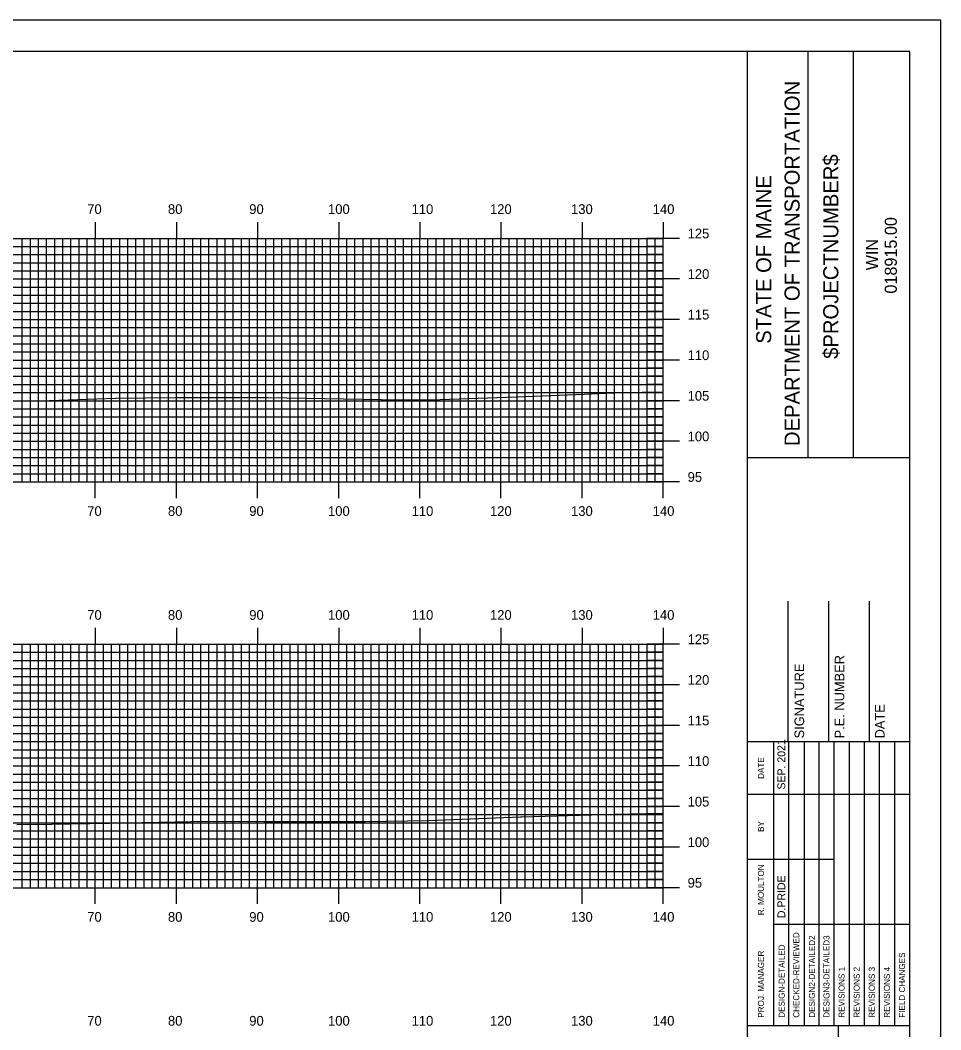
# Model space of a CAD drawing. Extents: x 1787763 to 1788106, y 442591 to 442811.
# Drawn here: x 1787989.4 to 1788102.8, y 442686.2 to 442810.5 of the extents above; entities that cross this region are included whole.
import ezdxf

# ---------------------------------------------------------------- set-up
doc = ezdxf.new("R2010")
doc.units = 0
for name, color, linetype in [('BORDER', 7, 'Continuous'), ('H_V ANNOTATION', 7, 'Continuous'), ('MAJOR', 7, 'Continuous'), ('MINOR', 7, 'Continuous'), ('PLOT BOUNDARY', 7, 'Continuous'), ('S_Roadway_Centerline', 7, 'Continuous')]:
    doc.layers.add(name, color=color, linetype=linetype)

msp = doc.modelspace()

# ---------------------------------------------------------------- linework, layer by layer
at = {"layer": 'BORDER'}
for p, q in [((1788079.02, 442596.67), (1788079.02, 442806.67)), ((1788086.47, 442756.66), (1788086.47, 442806.66)), ((1788092.06, 442756.66), (1788092.06, 442806.66)), ((1788079.02, 442756.65), (1788099.02, 442756.65)), ((1788084.02, 442721.67), (1788084.02, 442738.97)), ((1788089.02, 442721.67), (1788089.02, 442738.97)), ((1788094.02, 442721.67), (1788094.02, 442738.97)), ((1788079.02, 442721.67), (1788099.02, 442721.67)), ((1788079.02, 442686.67), (1788099.02, 442686.67)), ((1788090.2, 442616.67), (1788090.2, 442686.67))]:
    msp.add_line(p, q, dxfattribs=at)
msp.add_lwpolyline([(1787779.02, 442596.67), (1788099.02, 442596.67), (1788099.02, 442806.67), (1787779.02, 442806.67)], close=True, dxfattribs=at)
for points in [[(1788082.25, 442715.17), (1788082.25, 442721.67)], [(1788084.11, 442686.68), (1788084.11, 442721.67)], [(1788085.98, 442721.67), (1788085.98, 442686.68)], [(1788087.84, 442686.68), (1788087.84, 442721.67)], [(1788089.7, 442686.68), (1788089.7, 442721.67)], [(1788091.57, 442686.68), (1788091.57, 442721.67)], [(1788093.43, 442686.68), (1788093.43, 442721.67)], [(1788095.29, 442686.68), (1788095.29, 442721.67)], [(1788097.16, 442686.68), (1788097.16, 442721.67)], [(1788082.25, 442686.68), (1788082.25, 442720.26)], [(1788079.02, 442715.17), (1788099.02, 442715.17)], [(1788079.02, 442707.17), (1788082.25, 442707.17)], [(1788082.25, 442707.17), (1788089.7, 442707.17)], [(1788082.25, 442699.17), (1788099.02, 442699.17)]]:
    msp.add_lwpolyline(points, dxfattribs=at)
at = {"layer": 'MAJOR'}
for p, q in [((1787998.62, 442785.67), (1787998.62, 442783.67)), ((1788008.62, 442785.67), (1788008.62, 442783.67)), ((1788018.62, 442785.67), (1788018.62, 442783.67)), ((1788028.62, 442785.67), (1788028.62, 442783.67)), ((1788038.62, 442785.67), (1788038.62, 442783.67)), ((1788048.62, 442785.67), (1788048.62, 442783.67)), ((1788058.62, 442785.67), (1788058.62, 442783.67)), ((1788068.62, 442785.67), (1788068.62, 442783.67)), ((1787788.62, 442783.67), (1788068.62, 442783.67)), ((1787788.62, 442783.67), (1788068.62, 442783.67)), ((1787998.62, 442753.67), (1787998.62, 442783.67)), ((1788008.62, 442753.67), (1788008.62, 442783.67)), ((1788018.62, 442753.67), (1788018.62, 442783.67)), ((1788028.62, 442753.67), (1788028.62, 442783.67)), ((1788038.62, 442753.67), (1788038.62, 442783.67)), ((1788048.62, 442753.67), (1788048.62, 442783.67)), ((1788058.62, 442753.67), (1788058.62, 442783.67)), ((1788070.62, 442783.67), (1788066.61, 442783.67)), ((1788068.62, 442753.67), (1788068.62, 442783.67)), ((1788068.62, 442753.67), (1788068.62, 442783.67)), ((1787788.62, 442778.67), (1788068.62, 442778.67)), ((1788070.62, 442778.67), (1788066.61, 442778.67)), ((1787788.62, 442773.67), (1788068.62, 442773.67)), ((1788070.62, 442773.67), (1788066.61, 442773.67)), ((1787788.62, 442768.67), (1788068.62, 442768.67)), ((1788070.62, 442768.67), (1788066.61, 442768.67)), ((1787788.62, 442763.67), (1788068.62, 442763.67)), ((1788070.62, 442763.67), (1788066.61, 442763.67)), ((1787788.62, 442758.67), (1788068.62, 442758.67)), ((1788070.62, 442758.67), (1788066.61, 442758.67)), ((1787788.62, 442753.67), (1788068.62, 442753.67)), ((1787788.62, 442753.67), (1788068.62, 442753.67)), ((1787998.62, 442751.66), (1787998.62, 442753.67)), ((1788008.62, 442751.66), (1788008.62, 442753.67)), ((1788018.62, 442751.66), (1788018.62, 442753.67)), ((1788028.62, 442751.66), (1788028.62, 442753.67)), ((1788038.62, 442751.66), (1788038.62, 442753.67)), ((1788048.62, 442751.66), (1788048.62, 442753.67)), ((1788058.62, 442751.66), (1788058.62, 442753.67)), ((1788070.62, 442753.67), (1788066.61, 442753.67)), ((1788068.62, 442751.66), (1788068.62, 442753.67)), ((1787998.62, 442735.67), (1787998.62, 442733.67)), ((1788008.62, 442735.67), (1788008.62, 442733.67)), ((1788018.62, 442735.67), (1788018.62, 442733.67)), ((1788028.62, 442735.67), (1788028.62, 442733.67)), ((1788038.62, 442735.67), (1788038.62, 442733.67)), ((1788048.62, 442735.67), (1788048.62, 442733.67)), ((1788058.62, 442735.67), (1788058.62, 442733.67)), ((1788068.62, 442735.67), (1788068.62, 442733.67)), ((1787788.62, 442733.67), (1788068.62, 442733.67)), ((1787788.62, 442733.67), (1788068.62, 442733.67)), ((1787998.62, 442703.67), (1787998.62, 442733.67)), ((1788008.62, 442703.67), (1788008.62, 442733.67)), ((1788018.62, 442703.67), (1788018.62, 442733.67)), ((1788028.62, 442703.67), (1788028.62, 442733.67)), ((1788038.62, 442703.67), (1788038.62, 442733.67)), ((1788048.62, 442703.67), (1788048.62, 442733.67)), ((1788058.62, 442703.67), (1788058.62, 442733.67)), ((1788070.62, 442733.67), (1788066.61, 442733.67)), ((1788068.62, 442703.67), (1788068.62, 442733.67)), ((1788068.62, 442703.67), (1788068.62, 442733.67)), ((1787788.62, 442728.67), (1788068.62, 442728.67)), ((1788070.62, 442728.67), (1788066.61, 442728.67)), ((1787788.62, 442723.67), (1788068.62, 442723.67)), ((1788070.62, 442723.67), (1788066.61, 442723.67)), ((1787788.62, 442718.67), (1788068.62, 442718.67)), ((1788070.62, 442718.67), (1788066.61, 442718.67)), ((1787788.62, 442713.67), (1788068.62, 442713.67)), ((1788070.62, 442713.67), (1788066.61, 442713.67)), ((1787788.62, 442708.67), (1788068.62, 442708.67)), ((1788070.62, 442708.67), (1788066.61, 442708.67)), ((1787788.62, 442703.67), (1788068.62, 442703.67)), ((1787788.62, 442703.67), (1788068.62, 442703.67)), ((1787998.62, 442701.66), (1787998.62, 442703.67)), ((1788008.62, 442701.66), (1788008.62, 442703.67)), ((1788018.62, 442701.66), (1788018.62, 442703.67)), ((1788028.62, 442701.66), (1788028.62, 442703.67)), ((1788038.62, 442701.66), (1788038.62, 442703.67)), ((1788048.62, 442701.66), (1788048.62, 442703.67)), ((1788058.62, 442701.66), (1788058.62, 442703.67)), ((1788070.62, 442703.67), (1788066.61, 442703.67)), ((1788068.62, 442701.66), (1788068.62, 442703.67))]:
    msp.add_line(p, q, dxfattribs=at)
at = {"layer": 'MINOR'}
for p, q in [((1787989.62, 442753.67), (1787989.62, 442783.67)), ((1787990.62, 442753.67), (1787990.62, 442783.67)), ((1787991.62, 442753.67), (1787991.62, 442783.67)), ((1787992.62, 442753.67), (1787992.62, 442783.67)), ((1787993.62, 442753.67), (1787993.62, 442783.67)), ((1787994.62, 442753.67), (1787994.62, 442783.67)), ((1787995.62, 442753.67), (1787995.62, 442783.67)), ((1787996.62, 442753.67), (1787996.62, 442783.67)), ((1787997.62, 442753.67), (1787997.62, 442783.67)), ((1787999.62, 442753.67), (1787999.62, 442783.67)), ((1788000.62, 442753.67), (1788000.62, 442783.67)), ((1788001.62, 442753.67), (1788001.62, 442783.67)), ((1788002.62, 442753.67), (1788002.62, 442783.67)), ((1788003.62, 442753.67), (1788003.62, 442783.67)), ((1788004.62, 442753.67), (1788004.62, 442783.67)), ((1788005.62, 442753.67), (1788005.62, 442783.67)), ((1788006.62, 442753.67), (1788006.62, 442783.67)), ((1788007.62, 442753.67), (1788007.62, 442783.67)), ((1788009.62, 442753.67), (1788009.62, 442783.67)), ((1788010.62, 442753.67), (1788010.62, 442783.67)), ((1788011.62, 442753.67), (1788011.62, 442783.67)), ((1788012.62, 442753.67), (1788012.62, 442783.67)), ((1788013.62, 442753.67), (1788013.62, 442783.67)), ((1788014.62, 442753.67), (1788014.62, 442783.67)), ((1788015.62, 442753.67), (1788015.62, 442783.67)), ((1788016.62, 442753.67), (1788016.62, 442783.67)), ((1788017.62, 442753.67), (1788017.62, 442783.67)), ((1788019.62, 442753.67), (1788019.62, 442783.67)), ((1788020.62, 442753.67), (1788020.62, 442783.67)), ((1788021.62, 442753.67), (1788021.62, 442783.67)), ((1788022.62, 442753.67), (1788022.62, 442783.67)), ((1788023.62, 442753.67), (1788023.62, 442783.67)), ((1788024.62, 442753.67), (1788024.62, 442783.67)), ((1788025.62, 442753.67), (1788025.62, 442783.67)), ((1788026.62, 442753.67), (1788026.62, 442783.67)), ((1788027.62, 442753.67), (1788027.62, 442783.67)), ((1788029.62, 442753.67), (1788029.62, 442783.67)), ((1788030.62, 442753.67), (1788030.62, 442783.67)), ((1788031.62, 442753.67), (1788031.62, 442783.67)), ((1788032.62, 442753.67), (1788032.62, 442783.67)), ((1788033.62, 442753.67), (1788033.62, 442783.67)), ((1788034.62, 442753.67), (1788034.62, 442783.67)), ((1788035.62, 442753.67), (1788035.62, 442783.67)), ((1788036.62, 442753.67), (1788036.62, 442783.67)), ((1788037.62, 442753.67), (1788037.62, 442783.67)), ((1788039.62, 442753.67), (1788039.62, 442783.67)), ((1788040.62, 442753.67), (1788040.62, 442783.67)), ((1788041.62, 442753.67), (1788041.62, 442783.67)), ((1788042.62, 442753.67), (1788042.62, 442783.67)), ((1788043.62, 442753.67), (1788043.62, 442783.67)), ((1788044.62, 442753.67), (1788044.62, 442783.67)), ((1788045.62, 442753.67), (1788045.62, 442783.67)), ((1788046.62, 442753.67), (1788046.62, 442783.67)), ((1788047.62, 442753.67), (1788047.62, 442783.67)), ((1788049.62, 442753.67), (1788049.62, 442783.67)), ((1788050.62, 442753.67), (1788050.62, 442783.67)), ((1788051.62, 442753.67), (1788051.62, 442783.67)), ((1788052.62, 442753.67), (1788052.62, 442783.67)), ((1788053.62, 442753.67), (1788053.62, 442783.67)), ((1788054.62, 442753.67), (1788054.62, 442783.67)), ((1788055.62, 442753.67), (1788055.62, 442783.67)), ((1788056.62, 442753.67), (1788056.62, 442783.67)), ((1788057.62, 442753.67), (1788057.62, 442783.67)), ((1788059.62, 442753.67), (1788059.62, 442783.67)), ((1788060.62, 442753.67), (1788060.62, 442783.67)), ((1788061.62, 442753.67), (1788061.62, 442783.67)), ((1788062.62, 442753.67), (1788062.62, 442783.67)), ((1788063.62, 442753.67), (1788063.62, 442783.67)), ((1788064.62, 442753.67), (1788064.62, 442783.67)), ((1788065.62, 442753.67), (1788065.62, 442783.67)), ((1788066.62, 442753.67), (1788066.62, 442783.67)), ((1788067.62, 442753.67), (1788067.62, 442783.67)), ((1787788.62, 442782.67), (1788068.62, 442782.67)), ((1788068.62, 442782.67), (1788066.61, 442782.67)), ((1787788.62, 442781.67), (1788068.62, 442781.67)), ((1788068.62, 442781.67), (1788066.61, 442781.67)), ((1787788.62, 442780.67), (1788068.62, 442780.67)), ((1788068.62, 442780.67), (1788066.61, 442780.67)), ((1787788.62, 442779.67), (1788068.62, 442779.67)), ((1788068.62, 442779.67), (1788066.61, 442779.67)), ((1787788.62, 442777.67), (1788068.62, 442777.67)), ((1788068.62, 442777.67), (1788066.61, 442777.67)), ((1787788.62, 442776.67), (1788068.62, 442776.67)), ((1788068.62, 442776.67), (1788066.61, 442776.67)), ((1787788.62, 442775.67), (1788068.62, 442775.67)), ((1788068.62, 442775.67), (1788066.61, 442775.67)), ((1787788.62, 442774.67), (1788068.62, 442774.67)), ((1788068.62, 442774.67), (1788066.61, 442774.67)), ((1787788.62, 442772.67), (1788068.62, 442772.67)), ((1788068.62, 442772.67), (1788066.61, 442772.67)), ((1787788.62, 442771.67), (1788068.62, 442771.67)), ((1788068.62, 442771.67), (1788066.61, 442771.67)), ((1787788.62, 442770.67), (1788068.62, 442770.67)), ((1788068.62, 442770.67), (1788066.61, 442770.67)), ((1787788.62, 442769.67), (1788068.62, 442769.67)), ((1788068.62, 442769.67), (1788066.61, 442769.67)), ((1787788.62, 442767.67), (1788068.62, 442767.67)), ((1788068.62, 442767.67), (1788066.61, 442767.67)), ((1787788.62, 442766.67), (1788068.62, 442766.67)), ((1788068.62, 442766.67), (1788066.61, 442766.67)), ((1787788.62, 442765.67), (1788068.62, 442765.67)), ((1788068.62, 442765.67), (1788066.61, 442765.67)), ((1787788.62, 442764.67), (1788068.62, 442764.67)), ((1788068.62, 442764.67), (1788066.61, 442764.67)), ((1787788.62, 442762.67), (1788068.62, 442762.67)), ((1788068.62, 442762.67), (1788066.61, 442762.67)), ((1787788.62, 442761.67), (1788068.62, 442761.67)), ((1788068.62, 442761.67), (1788066.61, 442761.67)), ((1787788.62, 442760.67), (1788068.62, 442760.67)), ((1788068.62, 442760.67), (1788066.61, 442760.67)), ((1787788.62, 442759.67), (1788068.62, 442759.67)), ((1788068.62, 442759.67), (1788066.61, 442759.67)), ((1787788.62, 442757.67), (1788068.62, 442757.67)), ((1788068.62, 442757.67), (1788066.61, 442757.67)), ((1787788.62, 442756.67), (1788068.62, 442756.67)), ((1788068.62, 442756.67), (1788066.61, 442756.67)), ((1787788.62, 442755.67), (1788068.62, 442755.67)), ((1788068.62, 442755.67), (1788066.61, 442755.67)), ((1787788.62, 442754.67), (1788068.62, 442754.67)), ((1788068.62, 442754.67), (1788066.61, 442754.67)), ((1787788.62, 442732.67), (1788068.62, 442732.67)), ((1787989.62, 442703.67), (1787989.62, 442733.67)), ((1787990.62, 442703.67), (1787990.62, 442733.67)), ((1787991.62, 442703.67), (1787991.62, 442733.67)), ((1787992.62, 442703.67), (1787992.62, 442733.67)), ((1787993.62, 442703.67), (1787993.62, 442733.67)), ((1787994.62, 442703.67), (1787994.62, 442733.67)), ((1787995.62, 442703.67), (1787995.62, 442733.67)), ((1787996.62, 442703.67), (1787996.62, 442733.67)), ((1787997.62, 442703.67), (1787997.62, 442733.67)), ((1787999.62, 442703.67), (1787999.62, 442733.67)), ((1788000.62, 442703.67), (1788000.62, 442733.67)), ((1788001.62, 442703.67), (1788001.62, 442733.67)), ((1788002.62, 442703.67), (1788002.62, 442733.67)), ((1788003.62, 442703.67), (1788003.62, 442733.67)), ((1788004.62, 442703.67), (1788004.62, 442733.67)), ((1788005.62, 442703.67), (1788005.62, 442733.67)), ((1788006.62, 442703.67), (1788006.62, 442733.67)), ((1788007.62, 442703.67), (1788007.62, 442733.67)), ((1788009.62, 442703.67), (1788009.62, 442733.67)), ((1788010.62, 442703.67), (1788010.62, 442733.67)), ((1788011.62, 442703.67), (1788011.62, 442733.67)), ((1788012.62, 442703.67), (1788012.62, 442733.67)), ((1788013.62, 442703.67), (1788013.62, 442733.67)), ((1788014.62, 442703.67), (1788014.62, 442733.67)), ((1788015.62, 442703.67), (1788015.62, 442733.67)), ((1788016.62, 442703.67), (1788016.62, 442733.67)), ((1788017.62, 442703.67), (1788017.62, 442733.67)), ((1788019.62, 442703.67), (1788019.62, 442733.67)), ((1788020.62, 442703.67), (1788020.62, 442733.67)), ((1788021.62, 442703.67), (1788021.62, 442733.67)), ((1788022.62, 442703.67), (1788022.62, 442733.67)), ((1788023.62, 442703.67), (1788023.62, 442733.67)), ((1788024.62, 442703.67), (1788024.62, 442733.67)), ((1788025.62, 442703.67), (1788025.62, 442733.67)), ((1788026.62, 442703.67), (1788026.62, 442733.67)), ((1788027.62, 442703.67), (1788027.62, 442733.67)), ((1788029.62, 442703.67), (1788029.62, 442733.67)), ((1788030.62, 442703.67), (1788030.62, 442733.67)), ((1788031.62, 442703.67), (1788031.62, 442733.67)), ((1788032.62, 442703.67), (1788032.62, 442733.67)), ((1788033.62, 442703.67), (1788033.62, 442733.67)), ((1788034.62, 442703.67), (1788034.62, 442733.67)), ((1788035.62, 442703.67), (1788035.62, 442733.67)), ((1788036.62, 442703.67), (1788036.62, 442733.67)), ((1788037.62, 442703.67), (1788037.62, 442733.67)), ((1788039.62, 442703.67), (1788039.62, 442733.67)), ((1788040.62, 442703.67), (1788040.62, 442733.67)), ((1788041.62, 442703.67), (1788041.62, 442733.67)), ((1788042.62, 442703.67), (1788042.62, 442733.67)), ((1788043.62, 442703.67), (1788043.62, 442733.67)), ((1788044.62, 442703.67), (1788044.62, 442733.67)), ((1788045.62, 442703.67), (1788045.62, 442733.67)), ((1788046.62, 442703.67), (1788046.62, 442733.67)), ((1788047.62, 442703.67), (1788047.62, 442733.67)), ((1788049.62, 442703.67), (1788049.62, 442733.67)), ((1788050.62, 442703.67), (1788050.62, 442733.67)), ((1788051.62, 442703.67), (1788051.62, 442733.67)), ((1788052.62, 442703.67), (1788052.62, 442733.67)), ((1788053.62, 442703.67), (1788053.62, 442733.67)), ((1788054.62, 442703.67), (1788054.62, 442733.67)), ((1788055.62, 442703.67), (1788055.62, 442733.67)), ((1788056.62, 442703.67), (1788056.62, 442733.67)), ((1788057.62, 442703.67), (1788057.62, 442733.67)), ((1788059.62, 442703.67), (1788059.62, 442733.67)), ((1788060.62, 442703.67), (1788060.62, 442733.67)), ((1788061.62, 442703.67), (1788061.62, 442733.67)), ((1788062.62, 442703.67), (1788062.62, 442733.67)), ((1788063.62, 442703.67), (1788063.62, 442733.67)), ((1788064.62, 442703.67), (1788064.62, 442733.67)), ((1788065.62, 442703.67), (1788065.62, 442733.67)), ((1788068.62, 442732.67), (1788066.61, 442732.67)), ((1788066.62, 442703.67), (1788066.62, 442733.67)), ((1788067.62, 442703.67), (1788067.62, 442733.67)), ((1787788.62, 442731.67), (1788068.62, 442731.67)), ((1788068.62, 442731.67), (1788066.61, 442731.67)), ((1787788.62, 442730.67), (1788068.62, 442730.67)), ((1788068.62, 442730.67), (1788066.61, 442730.67)), ((1787788.62, 442729.67), (1788068.62, 442729.67)), ((1788068.62, 442729.67), (1788066.61, 442729.67)), ((1787788.62, 442727.67), (1788068.62, 442727.67)), ((1788068.62, 442727.67), (1788066.61, 442727.67)), ((1787788.62, 442726.67), (1788068.62, 442726.67)), ((1788068.62, 442726.67), (1788066.61, 442726.67)), ((1787788.62, 442725.67), (1788068.62, 442725.67)), ((1788068.62, 442725.67), (1788066.61, 442725.67)), ((1787788.62, 442724.67), (1788068.62, 442724.67)), ((1788068.62, 442724.67), (1788066.61, 442724.67)), ((1787788.62, 442722.67), (1788068.62, 442722.67)), ((1788068.62, 442722.67), (1788066.61, 442722.67)), ((1787788.62, 442721.67), (1788068.62, 442721.67)), ((1788068.62, 442721.67), (1788066.61, 442721.67)), ((1787788.62, 442720.67), (1788068.62, 442720.67)), ((1788068.62, 442720.67), (1788066.61, 442720.67)), ((1787788.62, 442719.67), (1788068.62, 442719.67)), ((1788068.62, 442719.67), (1788066.61, 442719.67)), ((1787788.62, 442717.67), (1788068.62, 442717.67)), ((1788068.62, 442717.67), (1788066.61, 442717.67)), ((1787788.62, 442716.67), (1788068.62, 442716.67)), ((1788068.62, 442716.67), (1788066.61, 442716.67)), ((1787788.62, 442715.67), (1788068.62, 442715.67)), ((1788068.62, 442715.67), (1788066.61, 442715.67)), ((1787788.62, 442714.67), (1788068.62, 442714.67)), ((1788068.62, 442714.67), (1788066.61, 442714.67)), ((1787788.62, 442712.67), (1788068.62, 442712.67)), ((1788068.62, 442712.67), (1788066.61, 442712.67)), ((1787788.62, 442711.67), (1788068.62, 442711.67)), ((1788068.62, 442711.67), (1788066.61, 442711.67)), ((1787788.62, 442710.67), (1788068.62, 442710.67)), ((1788068.62, 442710.67), (1788066.61, 442710.67)), ((1787788.62, 442709.67), (1788068.62, 442709.67)), ((1788068.62, 442709.67), (1788066.61, 442709.67)), ((1787788.62, 442707.67), (1788068.62, 442707.67)), ((1787788.62, 442706.67), (1788068.62, 442706.67)), ((1788068.62, 442707.67), (1788066.61, 442707.67)), ((1788068.62, 442706.67), (1788066.61, 442706.67)), ((1787788.62, 442705.67), (1788068.62, 442705.67)), ((1788068.62, 442705.67), (1788066.61, 442705.67)), ((1787788.62, 442704.67), (1788068.62, 442704.67)), ((1788068.62, 442704.67), (1788066.61, 442704.67))]:
    msp.add_line(p, q, dxfattribs=at)
at = {"layer": 'PLOT BOUNDARY'}
msp.add_lwpolyline([(1787762.83, 442590.55), (1788102.83, 442590.55), (1788102.83, 442810.55), (1787762.83, 442810.55)], close=True, dxfattribs=at)
at = {"layer": 'S_Roadway_Centerline'}
for points in [[(1787981.61, 442763.64), (1787991.77, 442763.65), (1788001.14, 442763.98), (1788008.46, 442764.08), (1788015.51, 442764.07), (1788019.87, 442764.06), (1788036.19, 442763.79), (1788038.43, 442763.76), (1788039.94, 442763.78), (1788051.67, 442764.18), (1788058.89, 442764.48), (1788063.44, 442764.68), (1788068.62, 442764.76)], [(1787988.93, 442711.44), (1787993.21, 442711.48), (1788000.31, 442711.6), (1788012.43, 442711.86), (1788019.47, 442711.83), (1788026.83, 442711.83), (1788031.83, 442711.83), (1788039.72, 442711.93), (1788051.01, 442712.39), (1788051.19, 442712.4), (1788062.65, 442712.72), (1788068.62, 442712.85)]]:
    msp.add_lwpolyline(points, dxfattribs=at)

# ---------------------------------------------------------------- texts
at = {"layer": 'BORDER'}
for s, height, p in [('DEPARTMENT OF TRANSPORTATION', 1.8635, (1788085.43, 442758.08)), ('$PROJECTNUMBER$', 1.8635, (1788090.2, 442768.82)), ('STATE OF MAINE', 1.8635, (1788081.93, 442770.69)), ('018915.00', 1.491, (1788097.41, 442776.86)), ('WIN', 1.491, (1788095.09, 442779.73)), ('P.E. NUMBER', 1.1811, (1788090.94, 442722.06)), ('SIGNATURE', 1.181, (1788085.98, 442722.06)), ('DATE', 1.181, (1788095.9, 442722.06)), ('SEP. 2021', 0.969, (1788083.66, 442715.76)), ('DATE', 0.743, (1788081.03, 442717.08)), ('BY', 0.743, (1788081.03, 442710.54)), ('R. MOULTON', 0.745, (1788081.03, 442700.28)), ('D.PRIDE', 0.969, (1788083.66, 442699.92)), ('CHECKED-REVIEWED', 0.7455, (1788085.38, 442687.65)), ('DESIGN2-DETAILED2', 0.7455, (1788087.32, 442687.65)), ('DESIGN3-DETAILED3', 0.7455, (1788089.11, 442687.65)), ('DESIGN-DETAILED', 0.7455, (1788083.59, 442687.65)), ('PROJ. MANAGER', 0.7455, (1788081.03, 442687.65)), ('FIELD CHANGES', 0.7455, (1788098.42, 442687.65)), ('REVISIONS 1', 0.7455, (1788090.97, 442687.65)), ('REVISIONS 2', 0.7455, (1788092.83, 442687.65)), ('REVISIONS 3', 0.7455, (1788094.7, 442687.65)), ('REVISIONS 4', 0.7455, (1788096.56, 442687.65))]:
    msp.add_text(s, height=height, rotation=90, dxfattribs=at).set_placement(p)
at = {"layer": 'H_V ANNOTATION'}
for s, p in [('70', (1787997.62, 442786.67)), ('80', (1788007.57, 442786.67)), ('90', (1788017.59, 442786.67)), ('100', (1788027.3, 442786.67)), ('110', (1788037.6, 442786.67)), ('120', (1788047.26, 442786.67)), ('130', (1788057.25, 442786.67)), ('140', (1788067.32, 442786.67)), ('125', (1788071.62, 442783.67)), ('120', (1788071.62, 442778.67)), ('115', (1788071.62, 442773.67)), ('110', (1788071.62, 442768.67)), ('105', (1788071.62, 442763.67)), ('100', (1788071.62, 442758.67)), ('95', (1788071.62, 442753.67)), ('70', (1787997.62, 442749.47)), ('80', (1788007.57, 442749.47)), ('90', (1788017.59, 442749.47)), ('100', (1788027.3, 442749.47)), ('110', (1788037.6, 442749.47)), ('120', (1788047.26, 442749.47)), ('130', (1788057.25, 442749.47)), ('140', (1788067.32, 442749.47)), ('70', (1787997.62, 442736.67)), ('80', (1788007.57, 442736.67)), ('90', (1788017.59, 442736.67)), ('100', (1788027.3, 442736.67)), ('110', (1788037.6, 442736.67)), ('120', (1788047.26, 442736.67)), ('130', (1788057.25, 442736.67)), ('140', (1788067.32, 442736.67)), ('125', (1788071.62, 442733.67)), ('120', (1788071.62, 442728.67)), ('115', (1788071.62, 442723.67)), ('110', (1788071.62, 442718.67)), ('105', (1788071.62, 442713.67)), ('100', (1788071.62, 442708.67)), ('95', (1788071.62, 442703.67)), ('70', (1787997.62, 442699.47)), ('80', (1788007.57, 442699.47)), ('90', (1788017.59, 442699.47)), ('100', (1788027.3, 442699.47)), ('110', (1788037.6, 442699.47)), ('120', (1788047.26, 442699.47)), ('130', (1788057.25, 442699.47)), ('140', (1788067.32, 442699.47)), ('70', (1787997.62, 442686.67)), ('80', (1788007.57, 442686.67)), ('90', (1788017.59, 442686.67)), ('100', (1788027.3, 442686.67)), ('110', (1788037.6, 442686.67)), ('120', (1788047.26, 442686.67)), ('130', (1788057.25, 442686.67)), ('140', (1788067.32, 442686.67))]:
    msp.add_text(s, height=1.2, dxfattribs=at).set_placement(p)

doc.saveas('drawing.dxf')
